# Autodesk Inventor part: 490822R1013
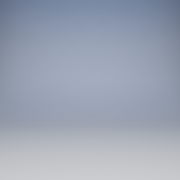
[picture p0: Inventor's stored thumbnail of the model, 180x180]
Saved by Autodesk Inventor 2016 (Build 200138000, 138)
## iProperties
Created: 2019-08
Part Number: 490822R1013
Material: 일반
Document SubType Name: Modeling
Designer: EDU-1-6
Density: 1 g/cm^3
Appearance: 기본값
Author: EDU-1-6
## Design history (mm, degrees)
